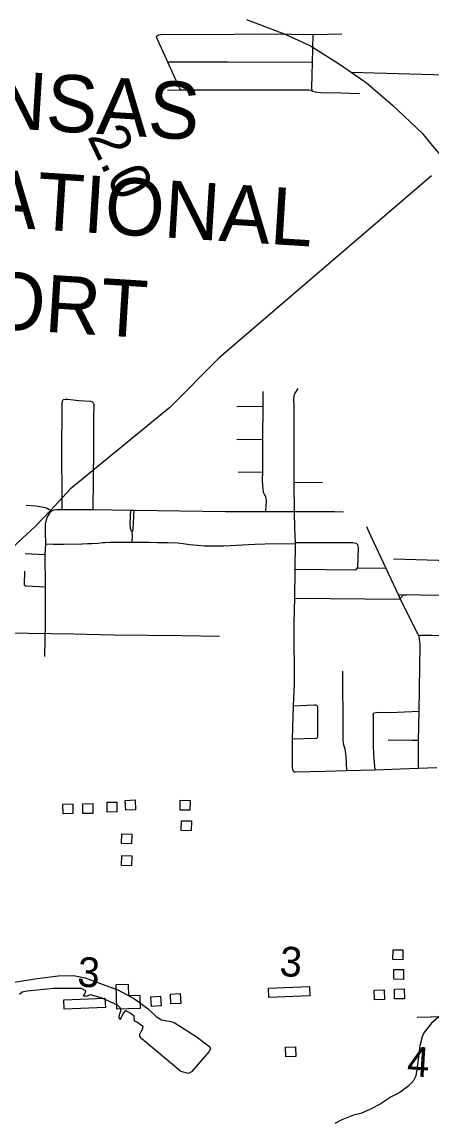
# Model space of a CAD drawing. Extents: x 1366406 to 1373462, y 376856 to 381998.
# Drawn here: x 1369072.6 to 1369121.6, y 380042.3 to 380173.9 of the extents above; entities that cross this region are included whole.
import ezdxf

# ---------------------------------------------------------------- set-up
doc = ezdxf.new("R2010")
doc.units = 0
for name, color, linetype in [('33', 7, 'Continuous'), ('34', 7, 'Continuous'), ('35', 7, 'Continuous'), ('43', 7, 'Continuous'), ('48', 7, 'Continuous'), ('56', 7, 'Continuous'), ('57', 7, 'Continuous'), ('58', 7, 'Continuous'), ('6', 7, 'Continuous')]:
    doc.layers.add(name, color=color, linetype=linetype)

msp = doc.modelspace()

# ---------------------------------------------------------------- linework, layer by layer
at = {"layer": '33'}
for p, q in [((1369098.24, 380127.87), (1369101.37, 380127.92)), ((1369098.25, 380123.93), (1369101.34, 380123.95)), ((1369098.41, 380120.02), (1369101.33, 380120.03))]:
    msp.add_line(p, q, dxfattribs=at)
for points in [[(1369091.53, 380165.72), (1369090.02, 380169.04), (1369088.69, 380171.98), (1369088.66, 380172.12), (1369088.76, 380172.26), (1369088.89, 380172.34), (1369089.12, 380172.36), (1369097.97, 380172.39), (1369102.34, 380172.43), (1369107.33, 380172.37), (1369110.81, 380172.43)], [(1369107.33, 380172.37), (1369107.25, 380169.03), (1369107.2, 380165.98), (1369107.22, 380165.61)], [(1369107.25, 380169.03), (1369097.22, 380169.06), (1369090.48, 380169.05), (1369090.02, 380169.04)], [(1369112.91, 380165.26), (1369110.72, 380165.33), (1369108.24, 380165.38), (1369107.68, 380165.45), (1369107.38, 380165.55), (1369107.22, 380165.61), (1369106.81, 380165.7), (1369091.53, 380165.72), (1369089.98, 380165.67)], [(1369105.56, 380130.03), (1369105.26, 380129.57), (1369105.2, 380129.45), (1369105.13, 380129.29), (1369105.06, 380129.07), (1369105.03, 380128.76), (1369105.07, 380127.8), (1369105.08, 380118.75), (1369105.13, 380115.25), (1369105.15, 380113.31), (1369105.24, 380111.58), (1369105.23, 380111.42), (1369105.19, 380108.4), (1369105.15, 380104.92), (1369105.09, 380101.93), (1369105.09, 380101.56), (1369105.1, 380094.72), (1369104.98, 380092.05), (1369104.88, 380088.05), (1369104.87, 380084.7), (1369104.92, 380084.4), (1369105.02, 380084.24), (1369105.13, 380084.17), (1369105.24, 380084.15), (1369108.84, 380084.23), (1369111.35, 380084.34), (1369114.77, 380084.42), (1369117.83, 380084.52), (1369119.94, 380084.58), (1369122.17, 380084.67)], [(1369077.39, 380115.56), (1369077.39, 380117.23), (1369077.34, 380122.25), (1369077.39, 380127.96), (1369077.4, 380128.21), (1369077.41, 380128.44), (1369077.44, 380128.55), (1369077.47, 380128.64), (1369077.54, 380128.7), (1369077.79, 380128.72), (1369078.06, 380128.73), (1369079.36, 380128.6)], [(1369079.36, 380128.6), (1369080.75, 380128.52), (1369080.98, 380128.44), (1369081.1, 380128.3), (1369081.15, 380128.13), (1369081.14, 380126.35), (1369081.13, 380122.73), (1369081.06, 380115.53)], [(1369101.37, 380129.67), (1369101.37, 380127.92), (1369101.34, 380123.95), (1369101.33, 380120.03), (1369101.28, 380119.12), (1369101.33, 380118.38), (1369101.35, 380118.03), (1369101.42, 380117.63), (1369101.52, 380117.37), (1369101.67, 380117.1), (1369101.73, 380116.9), (1369101.77, 380116.56), (1369101.68, 380115.3)], [(1369108.51, 380118.79), (1369105.08, 380118.75)], [(1369073.06, 380116.04), (1369074.24, 380115.98), (1369074.52, 380115.93), (1369074.9, 380115.88), (1369075.15, 380115.84), (1369075.34, 380115.78), (1369075.57, 380115.69), (1369075.78, 380115.59), (1369076.14, 380115.38)], [(1369075.3, 380097.97), (1369075.37, 380101.85), (1369075.38, 380106.28), (1369075.36, 380110.1), (1369075.42, 380111.45), (1369075.4, 380112.82), (1369075.4, 380113.5), (1369075.4, 380113.77), (1369075.41, 380113.95), (1369075.51, 380114.33), (1369075.59, 380114.57), (1369075.82, 380114.97), (1369075.99, 380115.21), (1369076.14, 380115.38), (1369076.43, 380115.52), (1369076.72, 380115.55), (1369077.39, 380115.56), (1369081.06, 380115.53), (1369085.53, 380115.46), (1369086, 380115.45), (1369096.89, 380115.29), (1369101.68, 380115.3), (1369109.91, 380115.29), (1369111, 380115.26)], [(1369085.53, 380115.46), (1369085.48, 380113.83), (1369085.51, 380113.31), (1369085.61, 380112.99), (1369085.71, 380112.92), (1369085.81, 380112.98), (1369085.88, 380113.16), (1369086, 380115.45)], [(1369085.71, 380112.92), (1369085.73, 380112.45), (1369085.71, 380111.63)], [(1369113.75, 380113.5), (1369114.23, 380112.42), (1369116.05, 380108.54), (1369117.55, 380105.37), (1369117.78, 380104.83), (1369119.87, 380100.7), (1369120, 380100.44), (1369120.05, 380100.05), (1369120.13, 380099.39), (1369120.02, 380091.4), (1369119.93, 380087.94), (1369119.94, 380084.58)], [(1369075.42, 380111.45), (1369076.31, 380111.4), (1369077.55, 380111.41), (1369079.79, 380111.42), (1369080.4, 380111.46), (1369080.94, 380111.49), (1369081.63, 380111.53), (1369082.24, 380111.59), (1369082.47, 380111.61), (1369083.06, 380111.63), (1369083.54, 380111.63), (1369084.55, 380111.63), (1369085.71, 380111.63), (1369086.85, 380111.64), (1369087.83, 380111.64), (1369088.76, 380111.61), (1369089.96, 380111.59), (1369091.16, 380111.54), (1369091.83, 380111.46), (1369092.61, 380111.37), (1369093.55, 380111.28), (1369094.38, 380111.2), (1369095.08, 380111.18), (1369095.8, 380111.2), (1369096.69, 380111.21), (1369100.41, 380111.39), (1369102.83, 380111.46), (1369105.23, 380111.42)], [(1369105.24, 380111.58), (1369112.13, 380111.59), (1369112.29, 380111.56), (1369112.53, 380111.51), (1369112.67, 380111.36), (1369112.72, 380111.19), (1369112.77, 380110.91), (1369112.69, 380108.58)], [(1369075.36, 380110.1), (1369072.95, 380110.22)], [(1369116.98, 380109.64), (1369123.68, 380109.43), (1369134.87, 380109.18)], [(1369072.89, 380108.18), (1369072.85, 380106.53), (1369072.95, 380106.43), (1369073.07, 380106.42), (1369075.38, 380106.28)], [(1369105.19, 380108.4), (1369112.42, 380108.32), (1369112.6, 380108.44), (1369112.69, 380108.58)], [(1369112.69, 380108.58), (1369116.05, 380108.54)], [(1369105.15, 380104.92), (1369117.78, 380104.83)], [(1369117.55, 380105.37), (1369118.16, 380105.35), (1369118.54, 380105.35), (1369119.17, 380105.36), (1369120.17, 380105.32), (1369123.55, 380105.28), (1369131.67, 380105.09), (1369134.82, 380104.99)], [(1369117.78, 380104.83), (1369117.86, 380105.01), (1369118.04, 380105.22), (1369118.16, 380105.35)], [(1369134.78, 380100.18), (1369124.72, 380100.34), (1369121.61, 380100.48), (1369120.22, 380100.48), (1369120, 380100.44)], [(1369110.87, 380096.22), (1369110.91, 380089.11), (1369110.91, 380088.57), (1369110.92, 380088.13), (1369110.93, 380087.91), (1369111.01, 380087.4), (1369111.15, 380086.9), (1369111.29, 380086.03), (1369111.35, 380084.34)], [(1369104.98, 380092.05), (1369107.52, 380092.17), (1369107.65, 380092.17), (1369107.77, 380092.15), (1369107.82, 380092.09), (1369107.87, 380092.04), (1369107.9, 380091.89), (1369107.9, 380088.46), (1369107.89, 380088.31), (1369107.85, 380088.24), (1369107.82, 380088.19), (1369107.76, 380088.16), (1369107.7, 380088.15), (1369104.88, 380088.05)], [(1369114.54, 380090.96), (1369114.55, 380091.08), (1369114.59, 380091.15), (1369114.69, 380091.21), (1369114.96, 380091.26), (1369115.61, 380091.28), (1369116.57, 380091.27), (1369120.02, 380091.4)], [(1369114.54, 380090.96), (1369114.54, 380089.01), (1369114.55, 380087.4), (1369114.61, 380086.2), (1369114.77, 380084.42)], [(1369116.34, 380087.98), (1369119.17, 380087.94), (1369119.93, 380087.94)], [(1369134.54, 380055.12), (1369130.41, 380055.06), (1369126.15, 380054.93), (1369119.8, 380054.76)]]:
    msp.add_lwpolyline(points, dxfattribs=at)
at = {"layer": '34'}
msp.add_lwpolyline([(1369121.52, 380155.46), (1369096.09, 380133.64), (1369090.24, 380127.74), (1369078.37, 380118.01), (1369075.99, 380115.43), (1369074.12, 380113.48), (1369072.13, 380111.64), (1369069.94, 380109.55), (1369068.47, 380108.26), (1369066.97, 380106.93), (1369066.12, 380106.07), (1369065.62, 380105.41), (1369065.16, 380104.88), (1369064.86, 380104.55), (1369063.51, 380103.55), (1369061.27, 380101.82), (1369059.69, 380100.66)], dxfattribs=at)
at = {"layer": '35'}
for points in [[(1369099.41, 380174.15), (1369104.12, 380172.35), (1369107.05, 380171), (1369110.42, 380168.88), (1369113.73, 380166.62), (1369116.88, 380163.9), (1369120.42, 380160.57), (1369121.4, 380159.31), (1369123.43, 380156.95)], [(1369071.66, 380059), (1369074.38, 380059.42), (1369076.92, 380059.76), (1369078.75, 380059.79), (1369080.11, 380059.52), (1369082.16, 380058.75), (1369084.04, 380058.08), (1369086.03, 380057), (1369087.65, 380055.8), (1369088.6, 380054.91), (1369089.26, 380054.51), (1369089.89, 380054.37), (1369090.21, 380054.35), (1369090.75, 380054.18), (1369093.38, 380052.51), (1369095.04, 380051.26), (1369095.12, 380051.03), (1369094.92, 380050.67), (1369092.85, 380048.28), (1369092.47, 380048.08), (1369091.57, 380048.32), (1369086.92, 380052.23), (1369086.66, 380052.52), (1369086.68, 380052.79), (1369086.84, 380053.1), (1369087.04, 380053.45), (1369087.05, 380053.68), (1369086.75, 380053.89), (1369086.4, 380054.18), (1369086, 380054.39), (1369086.01, 380054.48), (1369085.98, 380054.76), (1369085.99, 380054.94), (1369085.6, 380055.24), (1369085.24, 380055.44), (1369085.07, 380055.55), (1369084.93, 380055.56), (1369084.73, 380055.34), (1369084.53, 380054.99), (1369084.42, 380054.76), (1369084.32, 380054.59), (1369084.27, 380054.54), (1369084.19, 380054.69), (1369084.2, 380054.78), (1369084.22, 380055.14), (1369084.38, 380055.54), (1369084.4, 380055.86), (1369084.01, 380056.25), (1369082.15, 380057.1), (1369081.2, 380057.35), (1369080.75, 380057.47), (1369080.57, 380057.43), (1369080.47, 380057.35), (1369080.37, 380057.31), (1369080.19, 380057.32), (1369079.96, 380057.33), (1369079.92, 380057.43), (1369080.07, 380057.6), (1369080.18, 380057.78), (1369080.19, 380057.96), (1369079.69, 380058.24), (1369078.83, 380058.23), (1369077.55, 380058.26), (1369076.35, 380058.25), (1369073.19, 380057.94), (1369072.58, 380057.79), (1369072.29, 380057.54)], [(1369124.37, 380056.51), (1369121.52, 380054.1), (1369120.62, 380052.93), (1369120.4, 380052.47), (1369120.12, 380051.38), (1369119.83, 380048.78), (1369119.67, 380047.78), (1369119.33, 380047.17), (1369118.71, 380046.53), (1369117.75, 380045.8), (1369116.71, 380045.29), (1369115.38, 380044.41), (1369114.24, 380043.82), (1369113.08, 380043.29), (1369112.21, 380043.1), (1369110.79, 380042.52), (1369109.97, 380042.09)]]:
    msp.add_lwpolyline(points, dxfattribs=at)
at = {"layer": '43'}
msp.add_lwpolyline([(1369096.18, 380100.35), (1369091.69, 380100.43), (1369083.5, 380100.49), (1369078.74, 380100.61), (1369054.43, 380100.99), (1369048.55, 380100.94), (1369030.67, 380101.25), (1369017.89, 380101.43), (1369001.41, 380101.72)], dxfattribs=at)
at = {"layer": '56'}
for points in [[(1369077.5, 380079.14), (1369077.47, 380080.31), (1369078.64, 380080.34), (1369078.67, 380079.17)], [(1369079.87, 380079.17), (1369079.85, 380080.34), (1369081.03, 380080.36), (1369081.05, 380079.19)], [(1369082.76, 380079.35), (1369082.74, 380080.52), (1369083.92, 380080.53), (1369083.93, 380079.36)], [(1369084.98, 380079.58), (1369084.93, 380080.75), (1369086.1, 380080.8), (1369086.15, 380079.63)], [(1369091.47, 380079.59), (1369091.48, 380080.77), (1369092.66, 380080.75), (1369092.64, 380079.58)], [(1369091.62, 380077.13), (1369091.65, 380078.3), (1369092.82, 380078.28), (1369092.8, 380077.11)], [(1369084.49, 380075.57), (1369084.52, 380076.74), (1369085.69, 380076.71), (1369085.66, 380075.54)], [(1369084.49, 380072.97), (1369084.52, 380074.14), (1369085.69, 380074.1), (1369085.66, 380072.93)], [(1369116.92, 380061.71), (1369116.94, 380062.88), (1369118.11, 380062.86), (1369118.1, 380061.69)], [(1369117.01, 380059.34), (1369117.01, 380060.51), (1369118.18, 380060.5), (1369118.18, 380059.33)], [(1369090.38, 380056.39), (1369090.31, 380057.56), (1369091.48, 380057.63), (1369091.55, 380056.46)], [(1369102.08, 380057.16), (1369102.03, 380058.28), (1369106.95, 380058.48), (1369107, 380057.36)], [(1369114.73, 380056.87), (1369114.69, 380058.04), (1369115.87, 380058.08), (1369115.9, 380056.91)], [(1369117.12, 380056.99), (1369117.09, 380058.16), (1369118.26, 380058.19), (1369118.29, 380057.02)], [(1369077.62, 380055.76), (1369077.57, 380056.88), (1369082.49, 380057.08), (1369082.54, 380055.96)], [(1369088.04, 380056.09), (1369087.97, 380057.26), (1369089.15, 380057.33), (1369089.22, 380056.16)], [(1369104.12, 380050.06), (1369104.09, 380051.23), (1369105.27, 380051.27), (1369105.3, 380050.1)]]:
    msp.add_lwpolyline(points, close=True, dxfattribs=at)
at = {"layer": '58'}
msp.add_lwpolyline([(1369083.88, 380055.81), (1369086.74, 380055.89), (1369086.7, 380057.4), (1369085.34, 380057.36), (1369085.31, 380058.71), (1369083.8, 380058.67)], close=True, dxfattribs=at)
at = {"layer": '6'}
msp.add_line((1369111.91, 380167.87), (1369206.08, 380164.97), dxfattribs=at)

# ---------------------------------------------------------------- texts
at = {"layer": '48'}
msp.add_text('2.0', height=4.752, rotation=295.6107, dxfattribs=at).set_placement((1369080.33, 380160.16))
at = {"layer": '56'}
for s, p in [('3', (1369103.3, 380059.75)), ('3', (1369079.13, 380058.5)), ('4', (1369118.53, 380047.79))]:
    msp.add_text(s, height=3.56, rotation=356.4139, dxfattribs=at).set_placement(p)
at = {"layer": '57'}
for s, height, p in [('ARKANSAS', 6.843, (1369043.85, 380162.84)), ('INTERNATIONAL', 6.8429, (1369034.11, 380151.57)), ('AIRPORT', 6.843, (1369046.76, 380138.59))]:
    msp.add_text(s, height=height, rotation=356.4139, dxfattribs=at).set_placement(p)

doc.saveas('drawing.dxf')
